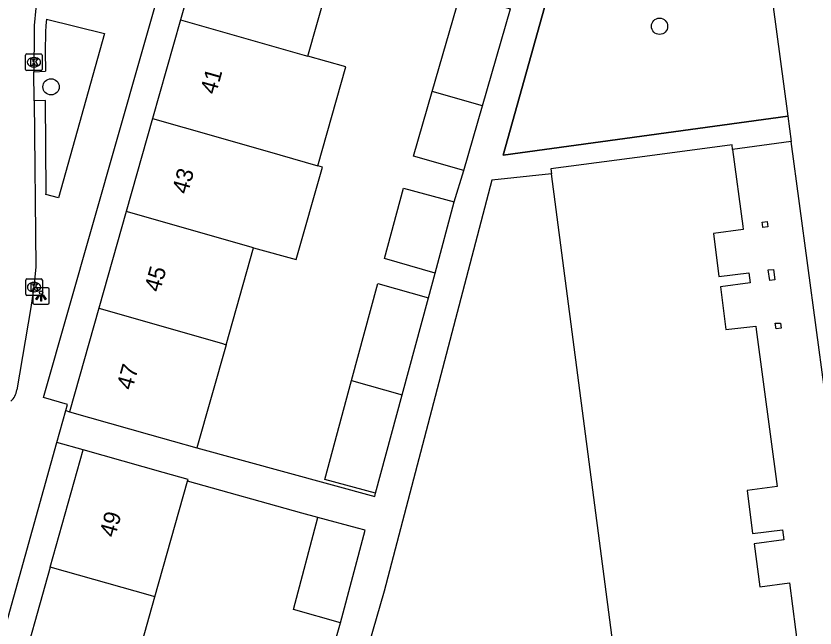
# Model space of a CAD drawing. Extents: x 163150 to 163546, y 380933 to 381635.
# Drawn here: x 163205.77 to 163253.82, y 381399.12 to 381435.94 of the extents above; entities that cross this region are included whole.
import ezdxf

# ---------------------------------------------------------------- set-up
doc = ezdxf.new("R2010")
doc.units = 0
for name, color, linetype in [('IMGEO_Boom', 7, 'Continuous'), ('IMGEO_Hek', 7, 'Continuous'), ('IMGEO_Kolk', 7, 'Continuous'), ('IMGEO_Lichtpunt', 7, 'Continuous'), ('IMGEO_Pand', 7, 'Continuous'), ('IMGEO_Pand_nummerreeks', 7, 'Continuous'), ('IMGEO_Parkeervlak_open', 7, 'Continuous'), ('IMGEO_Voetpad_open', 7, 'Continuous')]:
    doc.layers.add(name, color=color, linetype=linetype)

msp = doc.modelspace()

# ---------------------------------------------------------------- linework, layer by layer
at = {"layer": 'IMGEO_Boom'}
for centre in [(163244.469, 381435.322), (163207.876, 381431.678)]:
    msp.add_circle(centre, 0.489, dxfattribs=at)
at = {"layer": 'IMGEO_Hek'}
for points in [[(163235.062, 381427.567), (163238.676, 381440.476)], [(163252.186, 381429.92), (163235.062, 381427.567)]]:
    msp.add_lwpolyline(points, dxfattribs=at)
at = {"layer": 'IMGEO_Kolk'}
for p, q in [((163206.345, 381432.729), (163206.345, 381433.581)), ((163206.42, 381433.655), (163207.272, 381433.655)), ((163206.833, 381433.435), (163206.858, 381433.435)), ((163207.346, 381433.581), (163207.346, 381432.729)), ((163206.856, 381432.875), (163206.831, 381432.875)), ((163207.272, 381432.655), (163206.42, 381432.655)), ((163206.352, 381419.204), (163206.352, 381420.056)), ((163206.427, 381420.13), (163207.279, 381420.13)), ((163206.84, 381419.91), (163206.865, 381419.91)), ((163207.353, 381420.056), (163207.353, 381419.204)), ((163206.863, 381419.35), (163206.838, 381419.35)), ((163207.279, 381419.13), (163206.427, 381419.13))]:
    msp.add_line(p, q, dxfattribs=at)
for points in [[(163206.345, 381432.729), (163206.345, 381433.581)], [(163206.42, 381433.655), (163207.272, 381433.655)], [(163206.666, 381433.355), (163206.789, 381433.355), (163206.789, 381433.204), (163206.919, 381433.355), (163207.083, 381433.355), (163206.937, 381433.204), (163207.09, 381432.955), (163206.938, 381432.955), (163206.853, 381433.119), (163206.789, 381433.052), (163206.789, 381432.955), (163206.666, 381432.955), (163206.666, 381433.355)], [(163207.346, 381433.581), (163207.346, 381432.729)], [(163207.272, 381432.655), (163206.42, 381432.655)], [(163206.352, 381419.204), (163206.352, 381420.056)], [(163206.427, 381420.13), (163207.279, 381420.13)], [(163206.673, 381419.83), (163206.796, 381419.83), (163206.796, 381419.679), (163206.926, 381419.83), (163207.09, 381419.83), (163206.944, 381419.679), (163207.097, 381419.43), (163206.945, 381419.43), (163206.86, 381419.594), (163206.796, 381419.527), (163206.796, 381419.43), (163206.673, 381419.43), (163206.673, 381419.83)], [(163207.353, 381420.056), (163207.353, 381419.204)], [(163207.279, 381419.13), (163206.427, 381419.13)]]:
    msp.add_lwpolyline(points, dxfattribs=at)
for centre, start, end in [((163206.422, 381433.579), 91.552, 178.448), ((163206.422, 381433.579), 91.552, 178.448), ((163207.27, 381433.579), 1.552, 88.448), ((163207.27, 381433.579), 1.552, 88.448), ((163206.422, 381432.731), 181.552, 268.448), ((163206.422, 381432.731), 181.552, 268.448), ((163207.27, 381432.731), 271.552, 358.448), ((163207.27, 381432.731), 271.552, 358.448), ((163206.429, 381420.054), 91.552, 178.448), ((163206.429, 381420.054), 91.552, 178.448), ((163207.277, 381420.054), 1.552, 88.448), ((163207.277, 381420.054), 1.552, 88.448), ((163206.429, 381419.206), 181.552, 268.448), ((163206.429, 381419.206), 181.552, 268.448), ((163207.277, 381419.206), 271.552, 358.448), ((163207.277, 381419.206), 271.552, 358.448)]:
    msp.add_arc(centre, 0.0765, start, end, dxfattribs=at)
for centre, major_axis, ratio, start_param, end_param in [((163206.832, 381433.155), (-0.387, 0.002), 0.722429, 4.712389, 7.853982), ((163206.857, 381433.155), (-0.39, 0.002), 0.717154, 1.570796, 4.712389), ((163206.839, 381419.63), (-0.387, 0.002), 0.722429, 4.712389, 7.853982), ((163206.864, 381419.63), (-0.39, 0.002), 0.717154, 1.570796, 4.712389)]:
    msp.add_ellipse(centre, major_axis=major_axis, ratio=ratio, start_param=start_param, end_param=end_param, dxfattribs=at)
at = {"layer": 'IMGEO_Lichtpunt'}
for p, q in [((163206.776, 381419.501), (163206.776, 381418.694)), ((163206.776, 381419.501), (163206.776, 381418.694)), ((163207.678, 381419.596), (163206.87, 381419.596)), ((163207.678, 381419.596), (163206.87, 381419.596)), ((163207.772, 381418.694), (163207.772, 381419.501)), ((163207.772, 381418.694), (163207.772, 381419.501)), ((163206.87, 381418.6), (163207.678, 381418.6)), ((163206.87, 381418.6), (163207.678, 381418.6))]:
    msp.add_line(p, q, dxfattribs=at)
for points in [[(163207.15, 381419.165), (163207.189, 381419.137), (163207.001, 381418.875), (163206.963, 381418.902), (163207.15, 381419.165)], [(163207.252, 381419.117), (163207.299, 381419.117), (163207.299, 381418.795), (163207.252, 381418.795), (163207.252, 381419.117)], [(163207.362, 381419.137), (163207.4, 381419.164), (163207.587, 381418.902), (163207.548, 381418.874), (163207.362, 381419.137)]]:
    msp.add_lwpolyline(points, dxfattribs=at)
msp.add_circle((163207.275, 381419.299), 0.0994, dxfattribs=at)
for centre, start, end in [((163206.87, 381419.501), 90, 180), ((163206.87, 381419.501), 90, 180), ((163207.678, 381419.501), 0, 90), ((163207.678, 381419.501), 0, 90), ((163206.87, 381418.694), 180, 270), ((163206.87, 381418.694), 180, 270), ((163207.678, 381418.694), 270, 0), ((163207.678, 381418.694), 270, 360)]:
    msp.add_arc(centre, 0.0946, start, end, dxfattribs=at)
at = {"layer": 'IMGEO_Pand'}
for points in [[(163217.323, 381441.585), (163215.663, 381435.717)], [(163223.318, 381433.532), (163224.978, 381439.398)], [(163230.789, 381431.395), (163232.474, 381437.235), (163235.499, 381436.362)], [(163233.816, 381430.53), (163235.499, 381436.362)], [(163215.663, 381435.717), (163213.979, 381429.766)], [(163215.663, 381435.717), (163223.096, 381433.593), (163223.318, 381433.532)], [(163223.913, 381426.93), (163225.61, 381432.878), (163223.318, 381433.532)], [(163232.693, 381426.636), (163229.667, 381427.509), (163230.789, 381431.395)], [(163233.816, 381430.53), (163230.789, 381431.395)], [(163232.693, 381426.636), (163233.816, 381430.53)], [(163213.979, 381429.766), (163212.398, 381424.182)], [(163213.979, 381429.766), (163217.776, 381428.681), (163221.638, 381427.598), (163223.913, 381426.93)], [(163248.867, 381427.918), (163248.832, 381428.181), (163243.876, 381427.527), (163237.939, 381426.743), (163237.977, 381426.449)], [(163248.867, 381427.918), (163249.48, 381423.304), (163249.508, 381423.091), (163247.721, 381422.851), (163248.039, 381420.272), (163249.838, 381420.498), (163249.914, 381419.887), (163248.143, 381419.648), (163248.451, 381417.075), (163250.261, 381417.286), (163250.289, 381417.073), (163251.54, 381407.63), (163249.735, 381407.401), (163250.061, 381404.815), (163251.86, 381405.026), (163251.949, 381404.42), (163250.155, 381404.191), (163250.492, 381401.595), (163252.287, 381401.834), (163253.556, 381392.027)], [(163220.055, 381422.002), (163222.618, 381421.284), (163224.193, 381426.848), (163223.913, 381426.93)], [(163252.191, 381317.758), (163237.977, 381426.449)], [(163230.971, 381420.478), (163227.933, 381421.346), (163229.074, 381425.576), (163232.124, 381424.753)], [(163230.971, 381420.478), (163232.124, 381424.753)], [(163212.398, 381424.182), (163210.75, 381418.357)], [(163220.055, 381422.002), (163212.398, 381424.182)], [(163250.682, 381423.211), (163250.652, 381423.42), (163250.635, 381423.537), (163250.942, 381423.571), (163250.986, 381423.264), (163250.682, 381423.211)], [(163218.404, 381416.169), (163220.055, 381422.002)], [(163251.007, 381420.667), (163251.325, 381420.69), (163251.402, 381420.073), (163251.104, 381420.023), (163251.007, 381420.667)], [(163225.954, 381414.011), (163227.531, 381419.857), (163230.569, 381418.989)], [(163228.992, 381413.142), (163230.569, 381418.989)], [(163210.75, 381418.357), (163208.989, 381412.135)], [(163210.75, 381418.357), (163218.118, 381416.251), (163218.404, 381416.169)], [(163251.477, 381417.118), (163251.418, 381417.458), (163251.747, 381417.472), (163251.78, 381417.162), (163251.477, 381417.118)], [(163218.404, 381416.169), (163216.649, 381409.968)], [(163227.397, 381407.23), (163224.347, 381408.053), (163225.954, 381414.011)], [(163225.954, 381414.011), (163228.992, 381413.142)], [(163227.397, 381407.23), (163228.992, 381413.142)], [(163208.989, 381412.135), (163213.801, 381410.774), (163216.649, 381409.968)], [(163207.822, 381402.781), (163209.807, 381409.838)], [(163216.083, 381407.958), (163216.113, 381408.065), (163214.621, 381408.485), (163209.807, 381409.838)], [(163214.127, 381401.004), (163216.083, 381407.958)], [(163225.281, 381399.444), (163222.451, 381400.242), (163223.921, 381405.768)], [(163225.281, 381399.444), (163226.762, 381405.012), (163226.301, 381405.135), (163223.921, 381405.768)], [(163207.822, 381402.781), (163205.79, 381395.559)], [(163214.127, 381401.004), (163213.864, 381401.078), (163207.822, 381402.781)], [(163212.095, 381393.781), (163214.127, 381401.004)]]:
    msp.add_lwpolyline(points, dxfattribs=at)
at = {"layer": 'IMGEO_Parkeervlak_open'}
msp.add_lwpolyline([(163206.862, 381430.839), (163206.846, 381432.58)], dxfattribs=at)
at = {"layer": 'IMGEO_Voetpad_open'}
for points in [[(163208.756, 381412.2), (163208.859, 381412.568), (163207.416, 381412.989), (163222.262, 381465.047), (163223.737, 381464.635), (163226.121, 381473.3)], [(163245.713, 381465.817), (163238.676, 381440.476), (163235.062, 381427.567), (163252.186, 381429.92)], [(163247.511, 381464.766), (163252.186, 381429.92)], [(163209.838, 381448.544), (163206.97, 381436.404), (163206.869, 381435.376), (163206.852, 381434.394), (163206.841, 381433.156), (163206.846, 381432.58)], [(163207.598, 381435.755), (163211.091, 381434.896), (163208.33, 381425.004), (163207.572, 381425.199), (163207.588, 381425.3), (163207.541, 381430.863), (163206.862, 381430.839)], [(163206.846, 381432.58), (163207.547, 381432.629)], [(163206.862, 381430.839), (163206.951, 381420.855), (163206.849, 381419.63), (163206.667, 381418.408), (163205.816, 381413.457)], [(163252.186, 381429.92), (163252.391, 381428.393)], [(163252.391, 381428.393), (163248.867, 381427.918)], [(163270.661, 381292.68), (163258.396, 381383.641), (163252.391, 381428.393)], [(163232.124, 381424.753), (163232.693, 381426.636)], [(163237.977, 381426.449), (163234.394, 381426.061), (163227.903, 381401.347), (163219.779, 381373.21), (163217.039, 381362.987), (163210.152, 381338.67), (163208.061, 381330.864), (163204.278, 381316.746), (163202.976, 381313.355), (163198.372, 381299.184), (163184.779, 381256.196), (163183.349, 381256.587), (163188.12, 381274.155)], [(163230.569, 381418.989), (163230.971, 381420.478)], [(163208.221, 381410.28), (163208.756, 381412.2)], [(163208.756, 381412.2), (163208.989, 381412.135)], [(163194.052, 381359.469), (163208.221, 381410.28)], [(163209.807, 381409.838), (163208.221, 381410.28)], [(163216.649, 381409.968), (163227.347, 381407.045), (163227.397, 381407.23)], [(163223.921, 381405.768), (163222.952, 381406.026), (163216.083, 381407.958)], [(163224.861, 381397.979), (163225.281, 381399.444)]]:
    msp.add_lwpolyline(points, dxfattribs=at)
for centre, radius, start, end in [((163235.334, 381433.739), 27.81, 175.843, 182.2877), ((163204.805, 381413.554), 1.015, 309.3382, 354.5082)]:
    msp.add_arc(centre, radius, start, end, dxfattribs=at)

# ---------------------------------------------------------------- texts
at = {"layer": 'IMGEO_Pand_nummerreeks'}
for s, rotation, p in [('41', 74.198, (163217.784, 381431.171)), ('43', 74.198, (163216.087, 381425.172)), ('45', 74.1987, (163214.42, 381419.281)), ('47', 74.1987, (163212.753, 381413.391)), ('49', 74.2897, (163211.72, 381404.526))]:
    msp.add_text(s, height=1, rotation=rotation, dxfattribs=at).set_placement(p)

doc.saveas('drawing.dxf')
